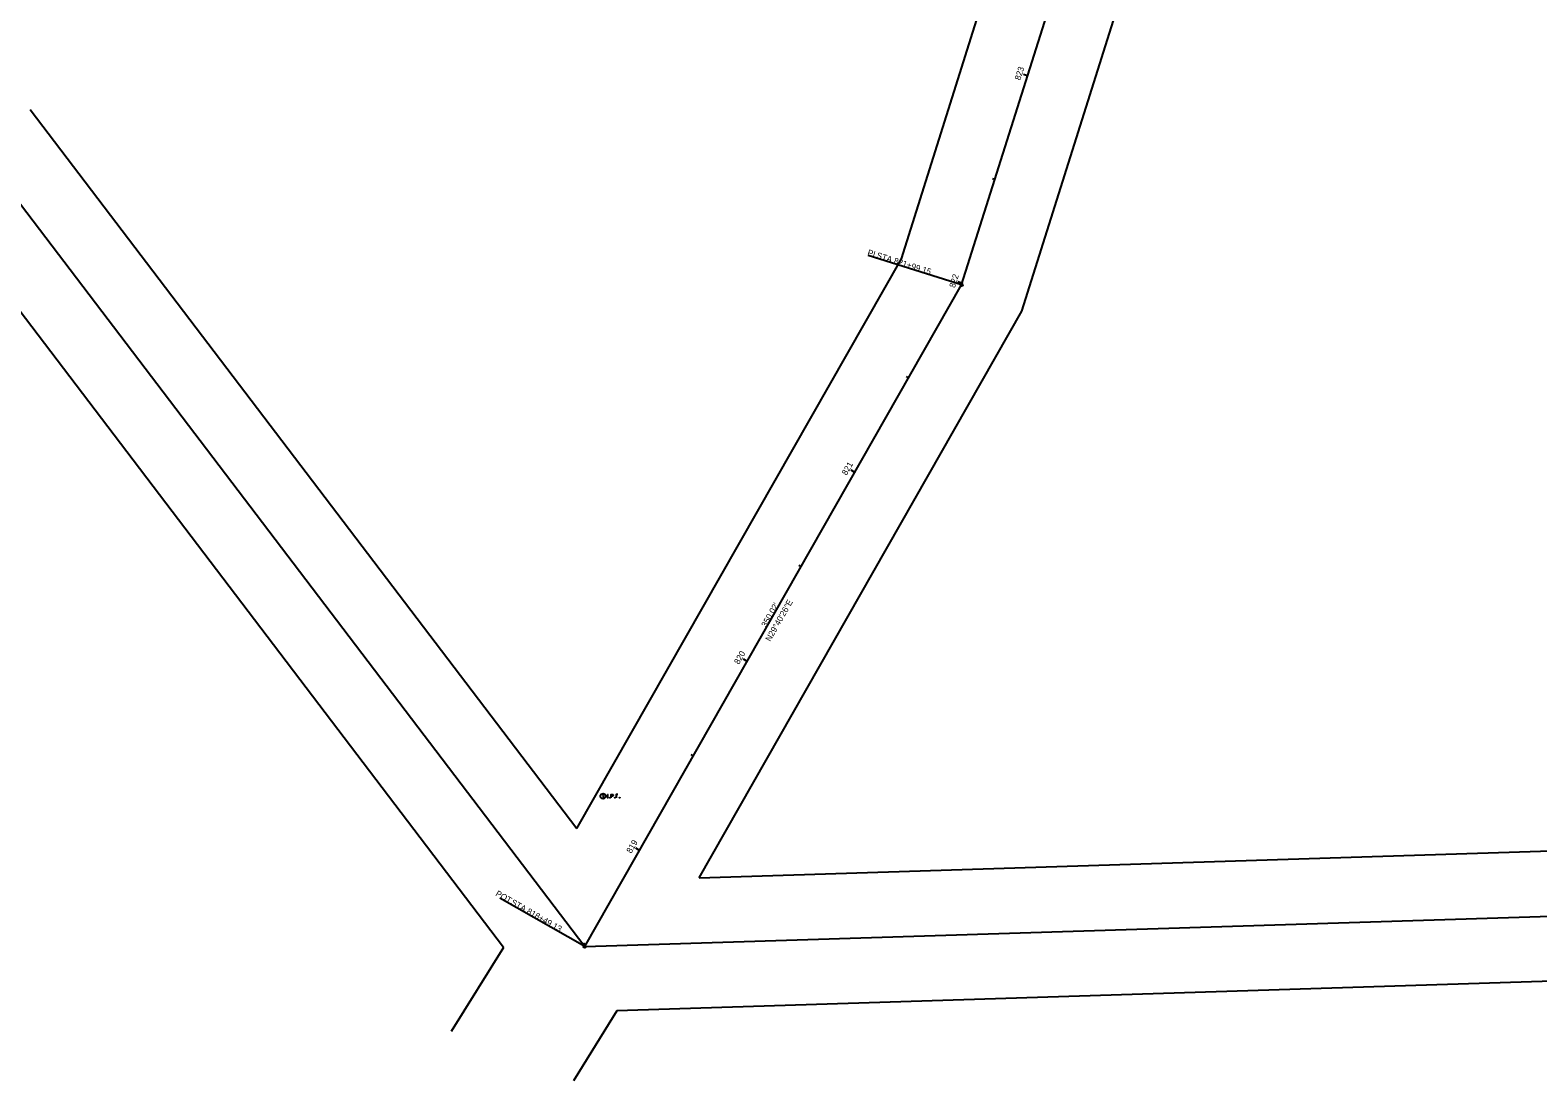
# Model space of a CAD drawing. Extents: x 2376935 to 2379466, y 252990 to 254108.
# Drawn here: x 2377507 to 2378201, y 252990 to 253473 of the extents above; entities that cross this region are included whole.
import ezdxf

# ---------------------------------------------------------------- set-up
doc = ezdxf.new("R2010")
doc.units = 0
for name, color, linetype in [('_CIVIL_CONSTRUCTION', 7, 'Continuous'), ('PF_P_Grade_Line', 7, 'Continuous'), ('PF_X_Ground_Line', 7, 'Continuous'), ('SC_Scratch1', 7, 'Continuous'), ('SC_Scratch2', 7, 'Continuous'), ('SN_X_Public', 7, 'Continuous'), ('UT_X_FO', 7, 'Continuous')]:
    doc.layers.add(name, color=color, linetype=linetype)

msp = doc.modelspace()

# ---------------------------------------------------------------- linework, layer by layer
at = {"layer": '_CIVIL_CONSTRUCTION'}
for p, q in [((2377965.9, 253451.66), (2377963.99, 253452.27)), ((2377950.86, 253403.98), (2377949.71, 253404.34)), ((2377935.82, 253356.29), (2377933.91, 253356.89)), ((2377911.23, 253312.78), (2377910.19, 253313.37)), ((2377886.48, 253269.34), (2377884.74, 253270.33)), ((2377861.73, 253225.89), (2377860.68, 253226.49)), ((2377836.97, 253182.45), (2377835.24, 253183.44)), ((2377812.22, 253139.01), (2377811.18, 253139.6)), ((2377787.47, 253095.56), (2377785.73, 253096.55)), ((2377762.72, 253052.12), (2377761.67, 253052.72))]:
    msp.add_line(p, q, dxfattribs=at)
at = {"layer": 'PF_P_Grade_Line'}
msp.add_line((2377770.71, 253120.65), (2377770.71, 253119.77), dxfattribs=at)
for points in [[(2377772.74, 253121.33), (2377773.1, 253121.33)], [(2377772.74, 253119.73), (2377773.1, 253119.73)], [(2377772.92, 253119.73), (2377772.92, 253121.33)], [(2377773.88, 253119.95), (2377773.93, 253119.95), (2377773.97, 253119.92), (2377774, 253119.87), (2377774, 253119.81), (2377773.97, 253119.76), (2377773.93, 253119.73), (2377773.88, 253119.73), (2377773.85, 253119.76), (2377773.81, 253119.81), (2377773.81, 253119.87), (2377773.85, 253119.92), (2377773.88, 253119.95)], [(2377774.48, 253119.73), (2377774.48, 253121.33), (2377775.01, 253121.33), (2377775.07, 253121.32), (2377775.15, 253121.3), (2377775.18, 253121.27), (2377775.21, 253121.24), (2377775.26, 253121.18), (2377775.29, 253121.12), (2377775.31, 253121.02), (2377775.31, 253120.87), (2377775.3, 253120.82), (2377775.28, 253120.74), (2377775.23, 253120.65), (2377775.19, 253120.61), (2377775.16, 253120.59), (2377775.1, 253120.56), (2377775.01, 253120.55), (2377774.48, 253120.55)], [(2377776.13, 253119.95), (2377776.18, 253119.95), (2377776.22, 253119.92), (2377776.25, 253119.87), (2377776.25, 253119.81), (2377776.22, 253119.76), (2377776.18, 253119.73), (2377776.13, 253119.73), (2377776.09, 253119.76), (2377776.06, 253119.81), (2377776.06, 253119.87), (2377776.09, 253119.92), (2377776.13, 253119.95)], [(2377777.49, 253121.33), (2377776.73, 253121.33), (2377776.73, 253119.73)], [(2377776.73, 253120.55), (2377777.27, 253120.55)], [(2377778.28, 253119.95), (2377778.33, 253119.95), (2377778.36, 253119.92), (2377778.4, 253119.87), (2377778.4, 253119.81), (2377778.36, 253119.76), (2377778.33, 253119.73), (2377778.28, 253119.73), (2377778.24, 253119.76), (2377778.21, 253119.81), (2377778.21, 253119.87), (2377778.24, 253119.92), (2377778.28, 253119.95)]]:
    msp.add_lwpolyline(points, dxfattribs=at)
for centre, radius in [((2377770.71, 253120.53), 1.2), ((2377770.71, 253121.18), 0.16)]:
    msp.add_circle(centre, radius, dxfattribs=at)
at = {"layer": 'PF_X_Ground_Line'}
for p, q in [((2377907.92, 253367.56), (2377995.3, 253644.64)), ((2377907.92, 253367.56), (2377995.3, 253644.64)), ((2377963.22, 253343.41), (2378052.52, 253626.6)), ((2377507.3, 253436.2), (2377758.69, 253105.65)), ((2377758.69, 253105.65), (2377907.92, 253367.56)), ((2377758.69, 253105.65), (2377907.92, 253367.56)), ((2377814.86, 253083.04), (2377963.22, 253343.41)), ((2377814.86, 253083.04), (2378258.76, 253097.09)), ((2377724.87, 253051), (2377700.91, 253012.27)), ((2377776.98, 253021.82), (2377757.09, 252989.66))]:
    msp.add_line(p, q, dxfattribs=at)
for points in [[(2377724.87, 253051), (2377460.91, 253398.09), (2377283.54, 253598.23), (2377191.69, 253704.44), (2376934.63, 254075.87)], [(2379401.65, 253044.72), (2379263.81, 253190.4), (2379127.05, 253209.14), (2379109.48, 253205.42), (2379029.66, 253188.5), (2378712.12, 253121.21), (2378265.28, 253037.26), (2377776.98, 253021.82)]]:
    msp.add_lwpolyline(points, dxfattribs=at)
at = {"layer": 'SC_Scratch1'}
for p, q in [((2377935.57, 253355.49), (2377892.65, 253369.02)), ((2377762.28, 253051.37), (2377723.19, 253073.64))]:
    msp.add_line(p, q, dxfattribs=at)
for centre in [(2377935.57, 253355.49), (2377762.28, 253051.37)]:
    msp.add_circle(centre, 0.6, dxfattribs=at)
at = {"layer": 'UT_X_FO'}
for p, q in [((2377935.57, 253355.49), (2378023.91, 253635.62)), ((2377484.1, 253417.14), (2377762.28, 253051.37)), ((2377484.1, 253417.14), (2377762.28, 253051.37)), ((2377762.28, 253051.37), (2377935.57, 253355.49)), ((2377762.28, 253051.37), (2378262.02, 253067.18)), ((2377762.28, 253051.37), (2378262.02, 253067.18))]:
    msp.add_line(p, q, dxfattribs=at)

# ---------------------------------------------------------------- texts
at = {"layer": '_CIVIL_CONSTRUCTION'}
for s, rotation, p in [('823', 72.49764, (2377962.55, 253449.37)), ('822', 72.49764, (2377932.47, 253353.98)), ('821', 60.32624, (2377882.71, 253267.77)), ('820', 60.32624, (2377833.18, 253180.85)), ('819', 60.32624, (2377783.7, 253094))]:
    msp.add_text(s, height=2.8, rotation=rotation, dxfattribs=at).set_placement(p)
at = {"layer": 'SC_Scratch1'}
for s, rotation, p in [('PI', 342.49764, (2377892.06, 253369.25)), (' STA. ', 342.49764, (2377895.22, 253368.25)), ('821+99.15', 342.49764, (2377904.11, 253365.45)), ('POT', 330.32624, (2377721, 253074.93)), (' STA. ', 330.32624, (2377727.2, 253071.4)), ('818+49.13', 330.32624, (2377735.3, 253066.78))]:
    msp.add_text(s, height=2.8, rotation=rotation, dxfattribs=at).set_placement(p)
at = {"layer": 'SC_Scratch2'}
msp.add_text("350.02'", height=2.8, rotation=60.32624, dxfattribs=at).set_placement((2377845.71, 253197.85))
at = {"layer": 'SN_X_Public'}
msp.add_text('N29°40\'26"E', height=2.8, rotation=60.32624, dxfattribs=at).set_placement((2377847.59, 253191.39))

doc.saveas('drawing.dxf')
